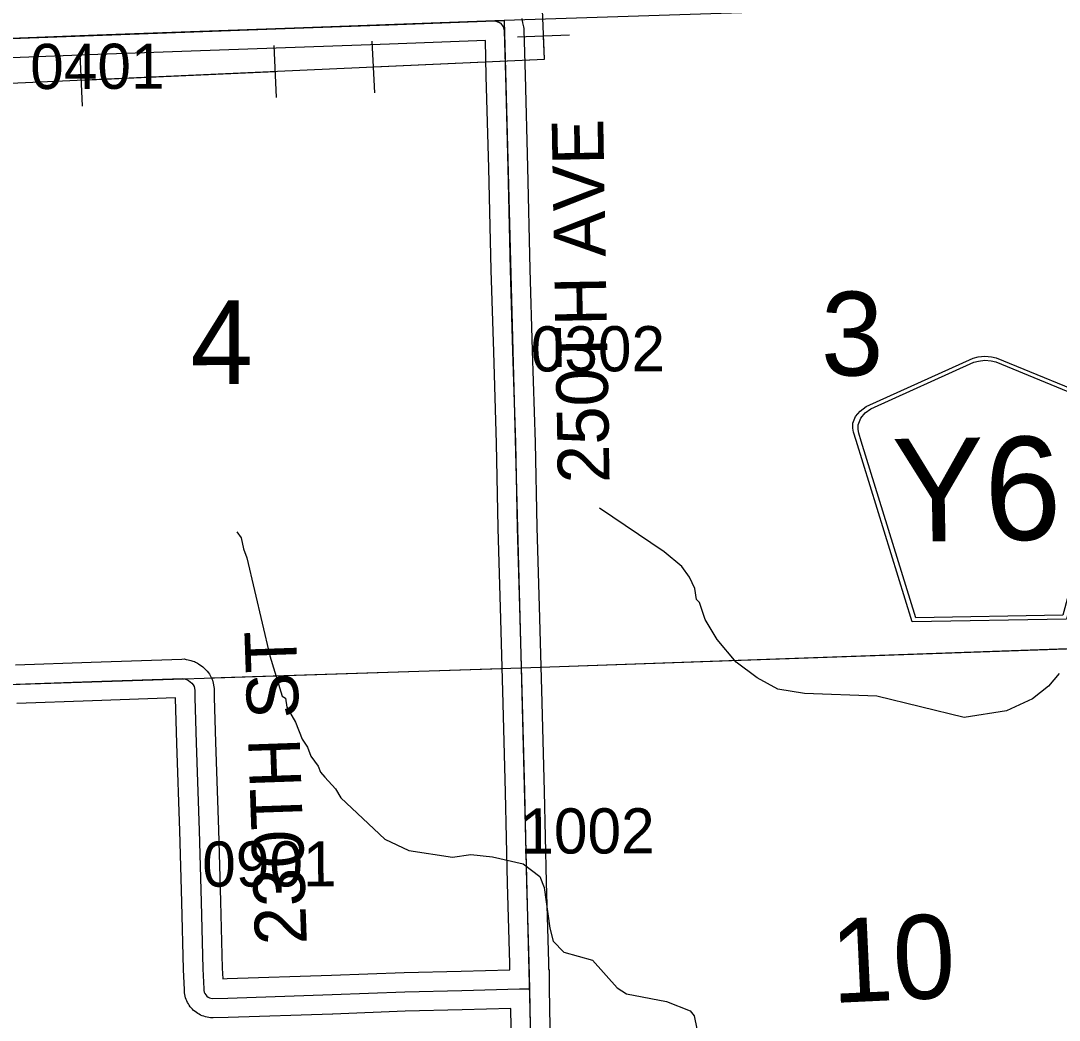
# Model space of a CAD drawing. Extents: x 128.7 to 185.5, y -21.4 to 12.6.
# Drawn here: x 148.442 to 150.052, y -8.801 to -7.251 of the extents above; entities that cross this region are included whole.
import ezdxf

# ---------------------------------------------------------------- set-up
doc = ezdxf.new("R2010")
doc.units = 0
for name, color, linetype in [('tdCoHydroRiver', 7, 'Continuous'), ('tdCoPipe', 7, 'Continuous'), ('tdCoSecRdNmbr', 7, 'Continuous'), ('tdCoSecRdTxt', 7, 'Continuous'), ('tdCoSecRteBand', 7, 'Continuous'), ('tdCoSecRteCL', 7, 'Continuous'), ('tdCoSectLine', 7, 'Continuous'), ('tdCoSectLinePart', 7, 'Continuous'), ('tdCoSectNmbr', 7, 'Continuous'), ('tdCoShieldCoRteHrd', 7, 'Continuous'), ('tdCoSurfGravel', 7, 'Continuous'), ('tdCoTwpBndryShd', 7, 'Continuous')]:
    doc.layers.add(name, color=color, linetype=linetype)

msp = doc.modelspace()

# ---------------------------------------------------------------- linework, layer by layer
at = {"layer": 'tdCoHydroRiver'}
for points in [[(150.052, -8.2636), (150.0353, -8.2831), (150.0108, -8.3029), (149.9704, -8.3217), (149.9044, -8.3318), (149.7691, -8.2986), (149.6569, -8.2945), (149.6157, -8.288), (149.5835, -8.2702), (149.5511, -8.2461), (149.5215, -8.2108), (149.5031, -8.1798), (149.4943, -8.1533), (149.4894, -8.1487), (149.4872, -8.1315), (149.4787, -8.1144), (149.4671, -8.0974), (149.4395, -8.0747), (149.3393, -8.0071)], [(148.7771, -8.0437), (148.7837, -8.053), (148.7875, -8.0702), (148.7927, -8.0842), (148.8279, -8.2361), (148.8474, -8.2986), (148.8522, -8.3016), (148.8543, -8.3157), (148.8677, -8.3389), (148.8781, -8.3654), (148.8864, -8.3777), (148.8916, -8.3918), (148.9032, -8.4072), (148.9067, -8.4165), (148.9133, -8.4242), (148.9297, -8.4425), (148.938, -8.4565), (149.0065, -8.5204), (149.0434, -8.5381), (149.1116, -8.5484), (149.1399, -8.5442), (149.1732, -8.5478), (149.2209, -8.5588), (149.2468, -8.5785), (149.2537, -8.5956), (149.2622, -8.6584), (149.2676, -8.6788), (149.284, -8.6956), (149.3286, -8.7082), (149.3664, -8.7511), (149.3809, -8.7601), (149.4429, -8.7722), (149.4797, -8.7867), (149.4862, -8.7944), (149.4901, -8.8148)]]:
    msp.add_lwpolyline(points, dxfattribs=at)
at = {"layer": 'tdCoPipe'}
for p, q in [((149.2927, -7.2736), (149.2122, -7.2769)), ((148.8387, -7.3701), (148.8351, -7.2895)), ((148.9907, -7.3633), (148.987, -7.2829)), ((148.5378, -7.3836), (148.5342, -7.3032))]:
    msp.add_line(p, q, dxfattribs=at)
for points in [[(141.1601, -9.4052), (141.1224, -8.4625), (145.143, -8.3469), (145.1432, -8.4836), (145.1432, -8.4836), (147.1541, -8.3987), (147.1541, -8.3987), (147.1261, -7.4066), (149.2539, -7.3111), (149.2196, -6.4561), (150.4341, -6.4227), (150.6653, -6.4146), (150.7655, -6.4047), (150.7905, -6.3931), (150.9328, -6.2039), (151.0021, -6.1768), (151.0811, -6.1651), (151.2121, -6.1436), (151.4086, -6.1336), (151.5974, -6.1255), (151.7034, -6.1214)], [(148.9889, -7.323), (149.2539, -7.3111), (149.2525, -7.2752)], [(148.536, -7.3433), (148.8369, -7.3298)]]:
    msp.add_lwpolyline(points, dxfattribs=at)
at = {"layer": 'tdCoSecRteBand'}
for points in [[(149.2186, -7.248), (149.22, -7.2546), (149.2212, -7.2606), (149.2217, -7.2632), (149.2218, -7.2658), (149.2238, -7.3356), (149.2238, -7.3357), (149.2238, -7.3357), (149.2275, -7.4785), (149.2275, -7.4785), (149.2275, -7.4785), (149.2314, -7.6363), (149.2351, -7.7627), (149.2396, -7.9052), (149.2396, -7.9053), (149.2396, -7.9055), (149.2423, -8.0366), (149.2462, -8.1775), (149.2462, -8.1776), (149.2462, -8.1776), (149.2497, -8.3083), (149.2534, -8.4464), (149.2534, -8.4464), (149.2534, -8.4465), (149.2566, -8.5872), (149.26, -8.7117), (149.26, -8.7118), (149.26, -8.7118), (149.2603, -8.7225), (149.261, -8.7225), (149.261, -8.7521), (149.263, -8.8413)], [(148.7551, -8.737), (148.7619, -8.7368), (148.9235, -8.7316), (149.0362, -8.7274), (149.0363, -8.7274), (149.0365, -8.7274), (149.1247, -8.7252), (149.2003, -8.7229), (149.2001, -8.7133), (149.1966, -8.5888), (149.1966, -8.5888), (149.1966, -8.5887), (149.1934, -8.4479), (149.1897, -8.3099), (149.1897, -8.3099), (149.1897, -8.3099), (149.1862, -8.1792), (149.1823, -8.0382), (149.1823, -8.038), (149.1823, -8.0379), (149.1796, -7.9069), (149.1752, -7.7645), (149.1752, -7.7645), (149.1752, -7.7645), (149.1715, -7.638), (149.1715, -7.6379), (149.1715, -7.6378), (149.1675, -7.48), (149.1638, -7.3373), (149.1623, -7.2822), (149.0137, -7.2878), (149.0136, -7.2878), (149.0136, -7.2878), (148.7063, -7.2986), (148.7063, -7.2986), (148.7063, -7.2986), (148.5613, -7.3036), (148.2263, -7.3164)], [(148.4338, -8.25), (148.5512, -8.2461), (148.6917, -8.2411), (148.6951, -8.241), (148.6985, -8.2416), (148.7017, -8.2423), (148.7038, -8.2427), (148.7059, -8.2434), (148.709, -8.2445), (148.7111, -8.2452), (148.713, -8.2462), (148.7159, -8.2477), (148.7178, -8.2487), (148.7196, -8.25), (148.7223, -8.2519), (148.7241, -8.2531), (148.7256, -8.2546), (148.728, -8.2569), (148.7296, -8.2584), (148.7309, -8.2601), (148.7329, -8.2627), (148.7345, -8.2647), (148.7356, -8.2668), (148.7371, -8.2696), (148.7395, -8.2739), (148.7403, -8.2788), (148.7413, -8.2845), (148.7417, -8.2867), (148.7418, -8.289), (148.742, -8.3008), (148.7437, -8.3701), (148.7486, -8.5058), (148.7487, -8.5059), (148.7487, -8.506), (148.7519, -8.6167), (148.7519, -8.6168), (148.7519, -8.6169), (148.7543, -8.7206), (148.7551, -8.737)], [(149.203, -8.8427), (149.2017, -8.7832), (149.2016, -8.7829), (149.1265, -8.7852), (149.1264, -8.7852), (149.1263, -8.7852), (149.0382, -8.7874), (148.9257, -8.7916), (148.9256, -8.7916), (148.9255, -8.7916), (148.7638, -8.7968), (148.7638, -8.7968), (148.7638, -8.7968), (148.7403, -8.7975), (148.7381, -8.7976), (148.736, -8.7973), (148.7335, -8.797), (148.7308, -8.7967), (148.7283, -8.796), (148.7259, -8.7952), (148.7233, -8.7945), (148.7209, -8.7933), (148.7187, -8.7921), (148.7163, -8.7909), (148.7142, -8.7893), (148.7122, -8.7878), (148.71, -8.7861), (148.7082, -8.7842), (148.7065, -8.7823), (148.7047, -8.7803), (148.7033, -8.7781), (148.702, -8.776), (148.7005, -8.7737), (148.6995, -8.7712), (148.6986, -8.7689), (148.6976, -8.7664), (148.697, -8.7638), (148.6965, -8.7613), (148.696, -8.7587), (148.6959, -8.756), (148.6958, -8.7538), (148.6944, -8.7231), (148.6944, -8.7227), (148.6943, -8.7224), (148.6919, -8.6184), (148.6887, -8.5078), (148.6838, -8.3721), (148.6837, -8.3719), (148.6837, -8.3717), (148.682, -8.3022), (148.682, -8.3021), (148.682, -8.3021), (148.682, -8.3015), (148.5533, -8.306), (148.5532, -8.306), (148.5532, -8.306), (148.4358, -8.31)]]:
    msp.add_lwpolyline(points, dxfattribs=at)
at = {"layer": 'tdCoSecRteCL'}
for points in [[(149.231, -8.7525), (149.23, -8.7125), (149.2266, -8.588), (149.2234, -8.4472), (149.2197, -8.3091), (149.2162, -8.1784), (149.2123, -8.0373), (149.2096, -7.9061), (149.2051, -7.7636), (149.2014, -7.6371), (149.1975, -7.4792), (149.1938, -7.3365), (149.1918, -7.2667), (149.1906, -7.2608), (149.1866, -7.2556), (149.1825, -7.2534), (149.1768, -7.2516), (149.0125, -7.2578), (148.7053, -7.2686), (148.5603, -7.2736), (148.2251, -7.2864), (148.1865, -7.2877)], [(148.4348, -8.28), (148.5522, -8.276), (148.6928, -8.2711), (148.696, -8.2717), (148.6992, -8.2728), (148.7021, -8.2744), (148.7048, -8.2763), (148.7072, -8.2786), (148.7093, -8.2812), (148.7108, -8.2839), (148.7118, -8.2896), (148.712, -8.3014), (148.7137, -8.371), (148.7187, -8.5069), (148.7219, -8.6176), (148.7243, -8.7217), (148.7258, -8.7527), (148.7259, -8.7552), (148.7264, -8.7576), (148.7273, -8.76), (148.7287, -8.7621), (148.7303, -8.7639), (148.7323, -8.7654), (148.7345, -8.7665), (148.7369, -8.7672), (148.7394, -8.7675), (148.7628, -8.7668), (148.9246, -8.7616), (149.0373, -8.7574), (149.1256, -8.7552), (149.2153, -8.7525), (149.231, -8.7525)], [(149.2371, -9.0048), (149.2365, -8.9794), (149.233, -8.842), (149.231, -8.7525)]]:
    msp.add_lwpolyline(points, dxfattribs=at)
at = {"layer": 'tdCoSectLine'}
for points in [[(148.1861, -7.2877), (149.1912, -7.251)], [(149.1912, -7.251), (149.2179, -8.2547)], [(149.2179, -8.2547), (150.2118, -8.2199)], [(148.203, -8.2879), (149.2179, -8.2547)], [(149.2179, -8.2547), (149.2433, -9.2552)]]:
    msp.add_lwpolyline(points, dxfattribs=at)
at = {"layer": 'tdCoSectLinePart'}
for points in [[(149.2479, -8.2537), (150.1819, -8.2209)], [(148.7368, -8.2705), (149.1881, -8.2557)]]:
    msp.add_lwpolyline(points, dxfattribs=at)
at = {"layer": 'tdCoShieldCoRteHrd'}
for points in [[(149.8239, -8.1837), (149.7371, -7.9023), (149.7329, -7.8892), (149.7321, -7.8833), (149.732, -7.8755), (149.736, -7.8651), (149.7432, -7.8565), (149.7526, -7.8497), (149.9186, -7.7744), (149.9261, -7.7726), (149.9365, -7.7715), (149.9469, -7.7723), (149.9545, -7.7738), (150.123, -7.8432), (150.1327, -7.8497), (150.1401, -7.8581), (150.1445, -7.8683), (150.1447, -7.8761), (150.144, -7.882), (150.1404, -7.8952), (150.0634, -8.1795)], [(149.8297, -8.1773), (149.7451, -7.9034), (149.7412, -7.8909), (149.7404, -7.8852), (149.7403, -7.8777), (149.7442, -7.8677), (149.751, -7.8595), (149.7601, -7.8529), (149.9194, -7.7807), (149.9266, -7.779), (149.9366, -7.7779), (149.9466, -7.7786), (149.9539, -7.7801), (150.1156, -7.8467), (150.125, -7.8529), (150.1321, -7.861), (150.1363, -7.8708), (150.1365, -7.8783), (150.1359, -7.884), (150.1324, -7.8967), (150.0574, -8.1733)]]:
    msp.add_lwpolyline(points, close=True, dxfattribs=at)
at = {"layer": 'tdCoSurfGravel'}
for points in [[(148.1865, -7.2877), (148.2251, -7.2864), (148.5603, -7.2736), (148.7053, -7.2686), (149.0125, -7.2578), (149.1768, -7.2516), (149.1825, -7.2534), (149.1866, -7.2556)], [(149.233, -8.842), (149.231, -8.7525), (149.23, -8.7125), (149.2266, -8.588), (149.2234, -8.4472), (149.2197, -8.3091), (149.2162, -8.1784), (149.2123, -8.0373), (149.2096, -7.9061), (149.2051, -7.7636), (149.2014, -7.6371), (149.1975, -7.4792), (149.1938, -7.3365), (149.1918, -7.2667), (149.1906, -7.2608), (149.1866, -7.2556)], [(148.4348, -8.28), (148.5522, -8.276), (148.6928, -8.2711), (148.696, -8.2717), (148.6992, -8.2728), (148.7021, -8.2744), (148.7048, -8.2763), (148.7072, -8.2786), (148.7093, -8.2812), (148.7108, -8.2839), (148.7118, -8.2896), (148.712, -8.3014), (148.7137, -8.371), (148.7187, -8.5069), (148.7219, -8.6176), (148.7243, -8.7217), (148.7258, -8.7527), (148.7259, -8.7552), (148.7264, -8.7576), (148.7273, -8.76), (148.7287, -8.7621), (148.7303, -8.7639), (148.7323, -8.7654), (148.7345, -8.7665), (148.7369, -8.7672), (148.7394, -8.7675), (148.7628, -8.7668), (148.9246, -8.7616), (149.0373, -8.7574), (149.1256, -8.7552), (149.2153, -8.7525), (149.231, -8.7525)]]:
    msp.add_lwpolyline(points, dxfattribs=at)
at = {"layer": 'tdCoTwpBndryShd'}
msp.add_lwpolyline([(150.395, -13.7476), (150.378, -13.2238), (150.3466, -12.2212), (150.3134, -11.2212), (150.2794, -10.2174), (150.245, -9.219), (150.2118, -8.2199), (150.1854, -7.2186), (149.1912, -7.251), (148.1861, -7.2877), (147.1862, -7.3236), (146.1796, -7.3579), (145.1769, -7.3938), (144.1761, -7.4248), (143.1728, -7.4558), (142.1753, -7.4874), (141.1678, -7.5201), (140.1762, -7.5484), (139.1499, -7.567), (138.1783, -7.5984), (137.1762, -7.6276), (136.1739, -7.6508), (135.1725, -7.6763), (134.1612, -7.6994)], dxfattribs=at)

# ---------------------------------------------------------------- texts
at = {"layer": 'tdCoSecRdNmbr'}
for s, rotation, p in [('0401', 0.1126, (148.4567, -7.3572)), ('0302', 0.1132, (149.2327, -7.7952)), ('1002', 0.1132, (149.2166, -8.5429)), ('0901', 0.1128, (148.7234, -8.5941))]:
    msp.add_text(s, height=0.07, rotation=rotation, dxfattribs=at).set_placement(p)
at = {"layer": 'tdCoSecRdTxt'}
for s, rotation, p in [('250TH AVE', 91, (149.3549, -7.9678)), ('230TH ST', 92, (148.8856, -8.6831))]:
    msp.add_text(s, height=0.08, rotation=rotation, dxfattribs=at).set_placement(p)
at = {"layer": 'tdCoSectNmbr'}
for s, rotation, p in [('3', 0.1135, (149.6828, -7.8016)), ('4', 0.1127, (148.7052, -7.8149)), ('10', 2.6658, (149.7003, -8.7746))]:
    msp.add_text(s, height=0.13, rotation=rotation, dxfattribs=at).set_placement(p)
at = {"layer": 'tdCoShieldCoRteHrd'}
msp.add_text('Y62', height=0.16, rotation=1, dxfattribs=at).set_placement((149.7945, -8.0599))

doc.saveas('drawing.dxf')
